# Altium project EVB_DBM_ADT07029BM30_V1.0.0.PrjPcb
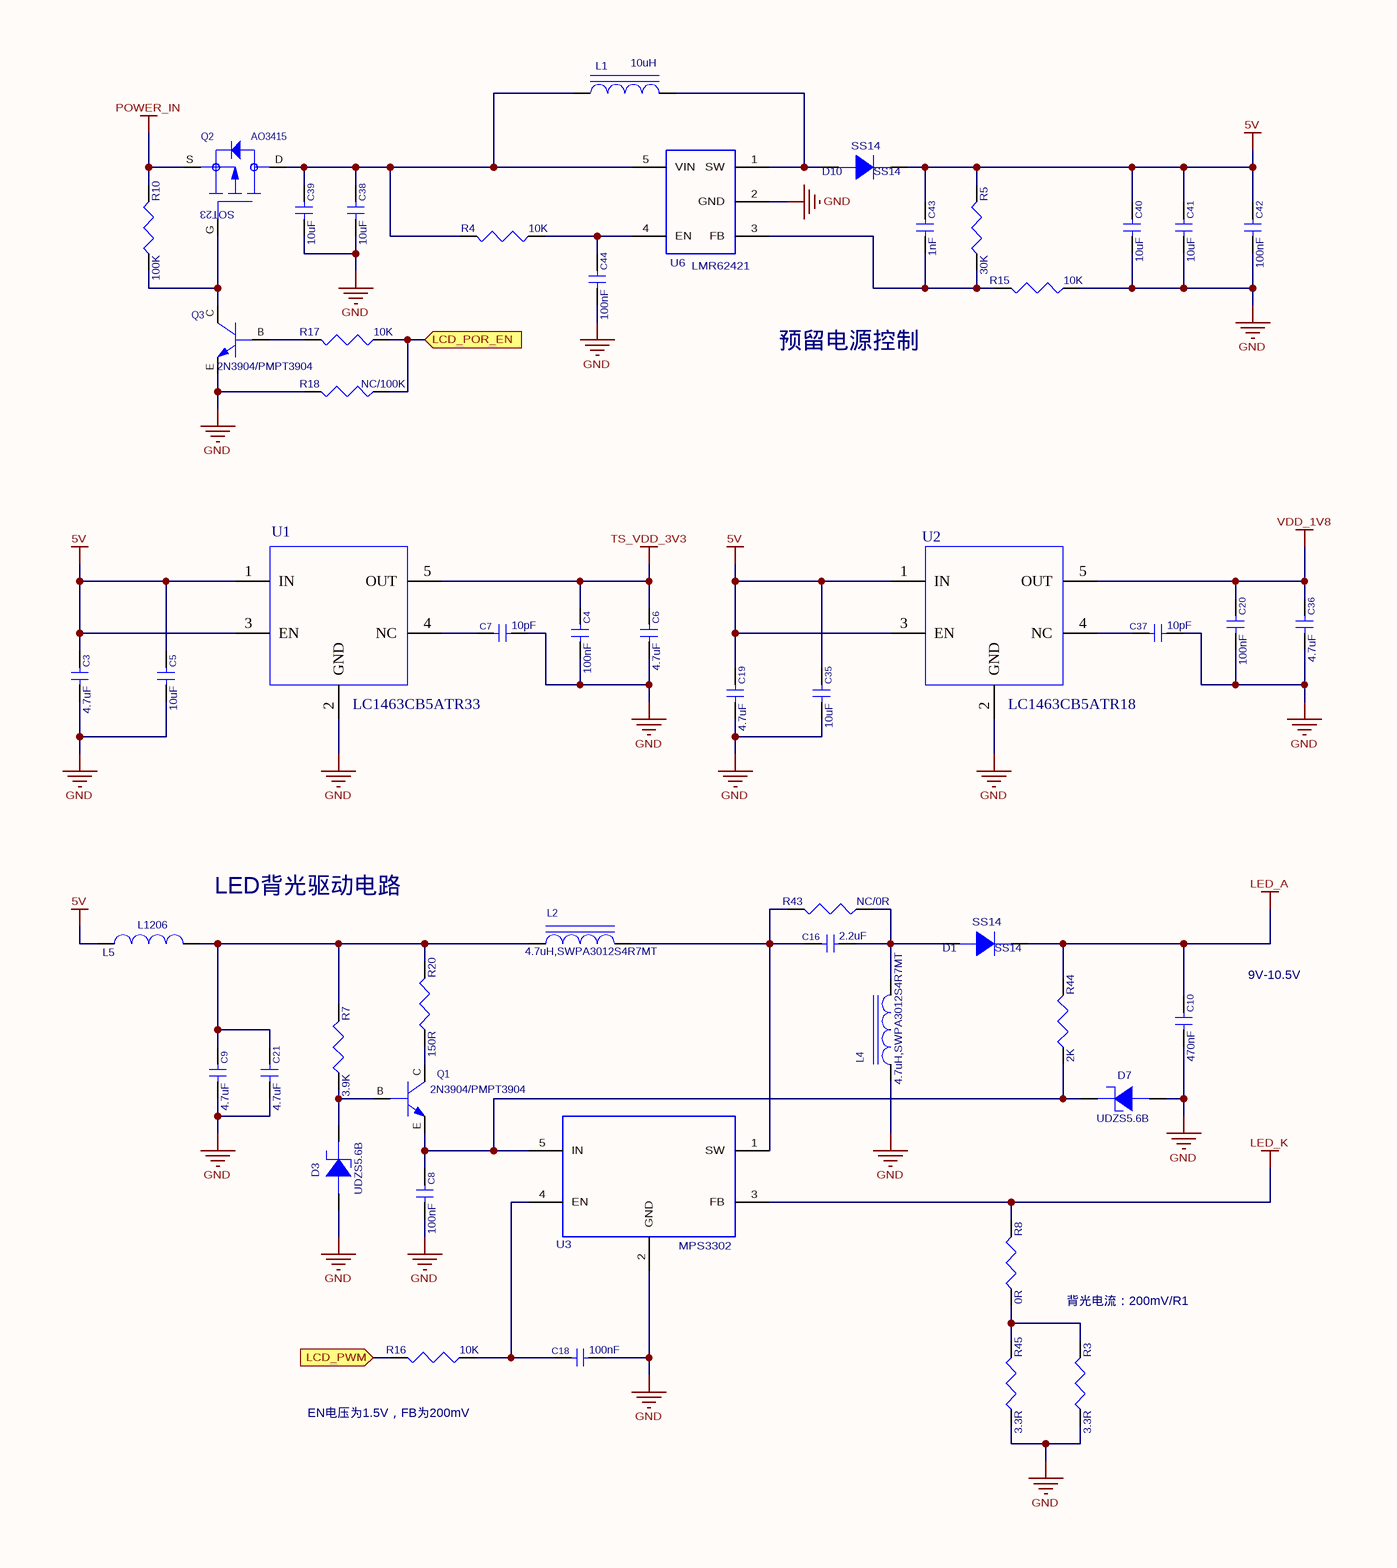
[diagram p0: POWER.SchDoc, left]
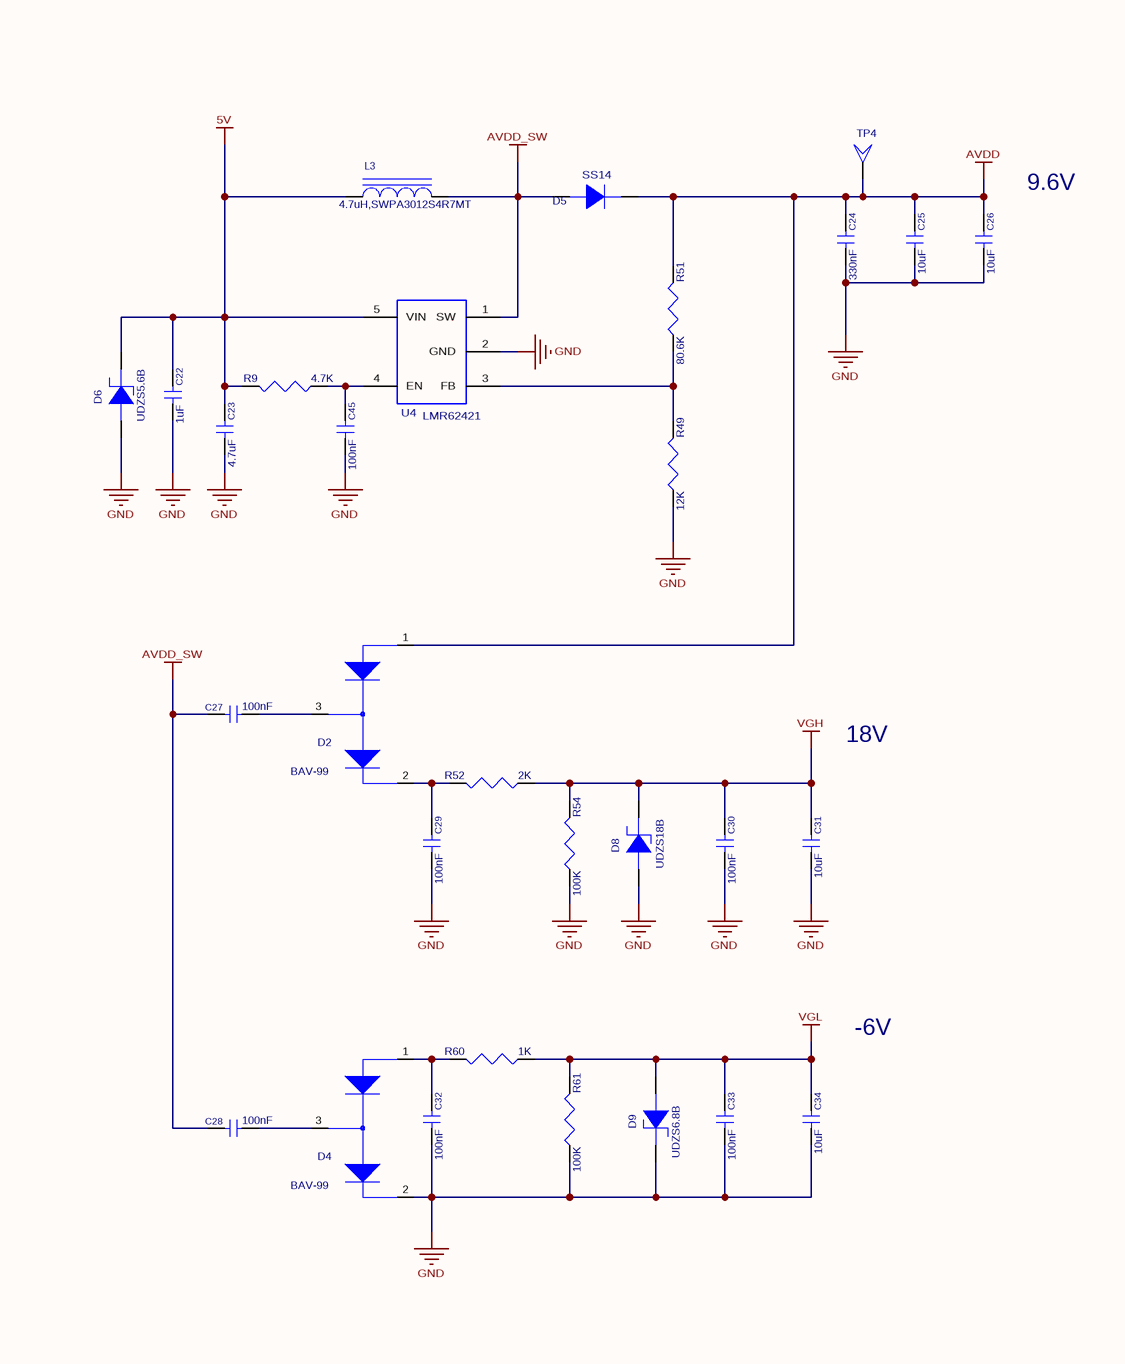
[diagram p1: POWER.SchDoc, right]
2 sheets, 113 parts. Net scope: flat (ports and power ports of the same name join across sheets).
Sheets:
  POWER.SchDoc
  CONNECT.SchDoc

## Sheet POWER.SchDoc: EVB_DBM_ADT07029BM30
size A3; Revision: V1.0.0; SheetNumber: 1; SheetTotal: 2; PCBPartNumber: Sky37D; PCBVersion: V1.0.0; SchModifyDate: 2020-4-27

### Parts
C3  4.7uF  [C0603]
C4  100nF  [C0603]
C5  10uF  [C0603]
C6  4.7uF  [C0603]
C7  10pF  [C0603]
C8  100nF  [C0603]
C9  4.7uF  [C0603]
C10  470nF  [C0603]
C16  2.2uF  [C0603]
C18  100nF  [C0603]
C19  4.7uF  [C0603]
C20  100nF  [C0603]
C21  4.7uF  [C0603]
C22  1uF  [C0603]
C23  4.7uF  [C0603]
C24  330nF  [C0603]
C25  10uF  [C0603]
C26  10uF  [C0603]
C27  100nF  [C0603]
C28  100nF  [C0603]
C29  100nF  [C0603]
C30  100nF  [C0603]
C31  10uF  [C0603]
C32  100nF  [C0603]
C33  100nF  [C0603]
C34  10uF  [C0603]
C35  10uF  [C0603]
C36  4.7uF  [C0603]
C37  10pF  [C0603]
C38  10uF  [C0603]
C39  10uF  [C0603]
C40  10uF  [C0603]
C41  10uF  [C0603]
C42  100nF  [C0603]
C43  1nF  [C0603]
C44  100nF  [C0603]
C45  100nF  [C0603]
D1  SS14  [SS14]
D2  BAV-99  [BAV-99_SOT23_123]
D3  UDZS5.6B  [UDZS6.8B]
D4  BAV-99  [BAV-99_SOT23_123]
D5  SS14  [SS14]  (value not drawn)
D6  UDZS5.6B  [UDZS6.8B]
D7  UDZS5.6B  [UDZS6.8B]
D8  UDZS18B  [UDZS6.8B]
D9  UDZS6.8B  [UDZS6.8B]
D10  SS14  [SS14]
L1  10uH  [L_SWPA4020_4X4MM]
L2  4.7uH,SWPA3012S4R7MT  [L_SWPA3012_3X3MM]
L3  4.7uH,SWPA3012S4R7MT  [L_SWPA3012_3X3MM]
L4  4.7uH,SWPA3012S4R7MT  [L_SWPA3012_3X3MM]
L5  L1206  [L1206]
Q1  value 2N3904/PMPT3904  [2N3904/PMBT3904]  (hidden comment: 2N3904/PMBT3904)
Q2  AO3415  [SOT23_GDS]
Q3  value 2N3904/PMPT3904  [2N3904/PMBT3904]  (hidden comment: 2N3904/PMBT3904)
R3  3.3R  [R0603]
R4  10K  [R0603]
R5  30K  [R0603]
R7  3.9K  [R0603]
R8  0R  [R0603]
R9  4.7K  [R0603]
R10  100K  [R0603]
R15  10K  [R0603]
R16  10K  [R0603]
R17  10K  [R0603]
R18  NC/100K  [R0603]
R20  150R  [R0603]
R43  NC/0R  [R0603]
R44  2K  [R0603]
R45  3.3R  [R0603]
R49  12K  [R0603]
R51  80.6K  [R0603]
R52  2K  [R0603]
R54  100K  [R0603]
R60  1K  [R0603]
R61  100K  [R0603]
TP4  TP40  [TP40]  (value not drawn)
U1  LC1463CB5ATR33  [LC1463CB5ATR18_SOT23-5]
U2  LC1463CB5ATR18  [LC1463CB5ATR18_SOT23-5]
U3  MPS3302  [MPS3302_SOT23-5]
U4  LMR62421  [MPS3302_SOT23-5]
U6  LMR62421  [MPS3302_SOT23-5]

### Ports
LCD_POR_EN (in), LCD_PWM (in)

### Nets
5V: C3.1 C5.1 C19.1 C22.1 C23.1 C35.1 C40.1 C41.1 C42.1 C43.1 D6.2(K) D10.K L3.1 L5.1 R5.2 R9.2 U1.1(IN) U1.3(EN) U2.1(IN) U2.3(EN) U4.5(VIN)
AVDD: C24.1 C25.1 C26.1 D2.1(GND) D5.K R51.2 TP4.1
AVDD_SW: C27.1 C28.1 D5.A L3.2 U4.1(SW)
GND: C3.2 C4.2 C5.2 C6.2 C7.2 C8.2 C9.2 C10.2 C18.2 C19.2 C20.2 C21.2 C22.2 C23.2 C24.2 C25.2 C26.2 C29.2 C30.2 C31.2 C32.2 C33.2 C34.2 C35.2 C36.2 C37.2 C38.2 C39.2 C40.2 C41.2 C42.2 C44.2 C45.2 D3.1(A) D4.2(VDD) D6.1(A) D7.1(A) D8.1(A) D9.2(K) L4.1 Q3.E R3.1 R15.1 R18.2 R45.1 R49.1 R54.1 R61.1 U1.2(GND) U2.2(GND) U3.2(GND) U4.2(GND) U6.2(GND)
LED_A: C10.1 D1.K R44.2
LED_K: R8.2 U3.3(FB)
POWER_IN: Q2.S R10.2
TS_VDD_3V3: C4.1 C6.1 U1.5(OUT)
VDD_1V8: C20.1 C36.1 U2.5(OUT)
VGH: C30.1 C31.1 D8.2(K) R52.1 R54.2
VGL: C33.1 C34.1 D9.1(A) R60.1 R61.2
LCD_POR_EN: R17.1 R18.1 ; port LCD_POR_EN
LCD_PWM: R16.2 ; port LCD_PWM
NetC7_1: C7.1 U1.4(NC)
NetC8_1: C8.1 D7.2(K) Q1.E R44.1 U3.5(IN)
NetC9_1: C9.1 C21.1 L2.1 L5.2 R7.2 R20.2
NetC16_1: C16.1 L2.2 R43.2 U3.1(SW)
NetC16_2: C16.2 D1.A L4.2 R43.1
NetC18_1: C18.1 R16.1 U3.4(EN)
NetC27_2: C27.2 D2.3(SIGNAL)
NetC28_2: C28.2 D4.3(SIGNAL)
NetC29_1: C29.1 D2.2(VDD) R52.2
NetC32_1: C32.1 D4.1(GND) R60.2
NetC37_1: C37.1 U2.4(NC)
NetC38_1: C38.1 C39.1 L1.1 Q2.D R4.2 U6.5(VIN)
NetC43_2: C43.2 R5.1 R15.2 U6.3(FB)
NetC44_1: C44.1 R4.1 U6.4(EN)
NetC45_1: C45.1 R9.1 U4.4(EN)
NetD3_2: D3.2(K) Q1.B R7.1
NetD10_A: D10.A L1.2 U6.1(SW)
NetQ1_C: Q1.C R20.1
NetQ2_G: Q2.G Q3.C R10.1
NetQ3_B: Q3.B R17.2
NetR3_2: R3.2 R8.1 R45.2
NetR49_2: R49.2 R51.1 U4.3(FB)

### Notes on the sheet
- (near C26) 9.6V
- 预留电源控制
- 18V
- (near L5) LED背光驱动电路
- 9V-10.5V
- -6V
- 背光电流：200mV/R1
- (near R16) EN电压为1.5V，FB为200mV

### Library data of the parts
C3 C6 C9 C19 C21 C23 C36 = CC0304752XX: C/C,4.7uF,10V +/-10%,0603; Catalog: 陶瓷电容
C4 C8 C18 C20 C27-C30 C32 C33 C42 C44 C45 = CC0301040XX: C/C,100nF,25V,+/-5%,0603; Catalog: 陶瓷电容
C5 C35 C38-C41 = CC0301064XX: C/C,10uF,6.3V,+/-20%,0603; Catalog: 陶瓷电容
C7 C37 = CC0301000XX: C/C,10pF,25V,+/-5%,0603; Catalog: 陶瓷电容
C10 = CC0304742XX: C/C,470nF,25V,+/-10%,0603; Catalog: 陶瓷电容
C16 = CC0302251XX: C/C,2.2uF,25V,+/-5%,,0603; Catalog: 陶瓷电容
C22 = CC0301052XX: C/C,1uF,50V,+/-5%,0603; Catalog: 陶瓷电容
C24 = CC0303340XX: C/C,330nF,50V,+/-5%,0603; Catalog: 陶瓷电容
C25 C26 C31 C34 = CC0301060XX: C/C,10uF,25V,+/-5%,0603; Catalog: 陶瓷电容
C43 = CC0301020XX: C/C,1nF,25V,+/-5%,0603; Catalog: 陶瓷电容
D1 D5 D10 = DDD0SCH00XX: SS14 DO-214AC 肖特基二极管; Catalog: 二极管
D2 D4 = DD21SSD00XX: Small signal Diodes,onsemi,BAV99LT1G,SOT23; Catalog: 二极管
D3 D6 D7 = DD23ZEN03XX: Zener Diode,UDZS5.6B,5.6V,S0D-323; Catalog: 二极管
D8 = DD23ZEN04XX: 稳压管：Zener Diode,UDZS18B,18V,S0D-323; PCB DECAL: UDZS5.6B; Catalog: 二极管
D9 = DD33ZEN68XX: Zener Diode,UDZS6.8B,6.8V,S0D-323; Catalog: 稳压管
L1 = WL1B01000XX: 10uH,SWPA4020S100MT; SOURCE_PATH: E:\工作目录\ORCAD原理图库\ORCAD元件库\磁珠&电感.OLB; Catalog: 贴片电感
L2-L4 = WL1C04R70XX: Part Number_AK: WL1C02R20XX; SOURCE_PATH: E:\工作目录\ORCAD原理图库\ORCAD元件库\磁珠&电感.OLB; Catalog: 贴片电感
L5 = BE0606010XX: PZ3216D601_L1206,PZ3216D601-1R5TF; SOURCE_PATH: E:\工作目录\ORCAD原理图库\ORCAD元件库\磁珠&电感.OLB; Catalog: 贴片磁珠
Q1 Q3 = TR05NGN00XX: 2N3904/PMBT3904,SOT-23,NPN,GP; PCB DECAL: 2N3904/PMBT3904_SOT23_BCE_NPN; Catalog: 三极管
Q2 = MS052SW02XX: AO3415-sot23,E-P-CH,GP; PCB DECAL: AO3413_SOT23_GDS_P; Catalog: MOS
R3 R45 = CR0303R30XX: Res,3.3R,1/10W,+/-5%,0603; Catalog: 贴片电阻
R4 R15-R17 = CR0310020XX: Res,10K,1/10W,+/-1%,0603; Catalog: 贴片电阻
R5 = CR0303030XX: Res,30K,1/10W,+/-5%,0603; Catalog: 贴片电阻
R7 = CR0339010XX: Res,3.9K,1/10W,+/-1%,0603; Catalog: 贴片电阻
R8 = CR0300000XX: Res,0R,1/10W,+/-5%,0603; Catalog: 贴片电阻
R9 = CR0304720XX: Res,4.7K,1/10W,+/-5%,0603; Catalog: 贴片电阻
R10 R18 R54 R61 = CR0310030XX: Res,100K,1/10W,+/-1%,0603; Catalog: 贴片电阻
R20 = CR0315000XX: Res,150R,1/10W,+/-1%,0603; Catalog: 贴片电阻
R43 = CR0300000XX: Res,0R,1/10W,+/-5%,0603; Remark: NC; Catalog: 贴片电阻
R44 R52 = CR0302020XX: Res,2K,1/10W,+/-5%,0603; Catalog: 贴片电阻
R49 = CR0312020XX: Res,12K,1/10W,+/-1%,0603; Catalog: 贴片电阻
R51 = CR0380620XX: Res,80.6k,1/10W,+/-1%,0603; Catalog: 贴片电阻
R60 = CR0301020XX: Res,1K,1/10W,+/-5%,0603; Catalog: 贴片电阻
U1 = JCSXTPW01X2: PowerIC,Leadchip,LC1463CB5ATR33,3.3V,SOT-23-5; Catalog: 集成电路
U2 = JCSXTPW61XX: PowerIC,Leadchip,LC1463CB5ATR18 ,SOT23,5pin; Catalog: 集成电路
U3 = JCSOTDR00XX: IC MP3302，LCD Drives LED，TSOT23-5; Catalog: 集成电路
U4 U6 = JCSOTPW27XX: PowerIC，TI,LMR62421，SOT-23; PCB DECAL: LMR62421_SOT23-5; Catalog: 集成电路

## Sheet CONNECT.SchDoc: EVB_DBM_ADT07029BM30
size A3; Revision: V1.0.0; SheetNumber: 2; SheetTotal: 2
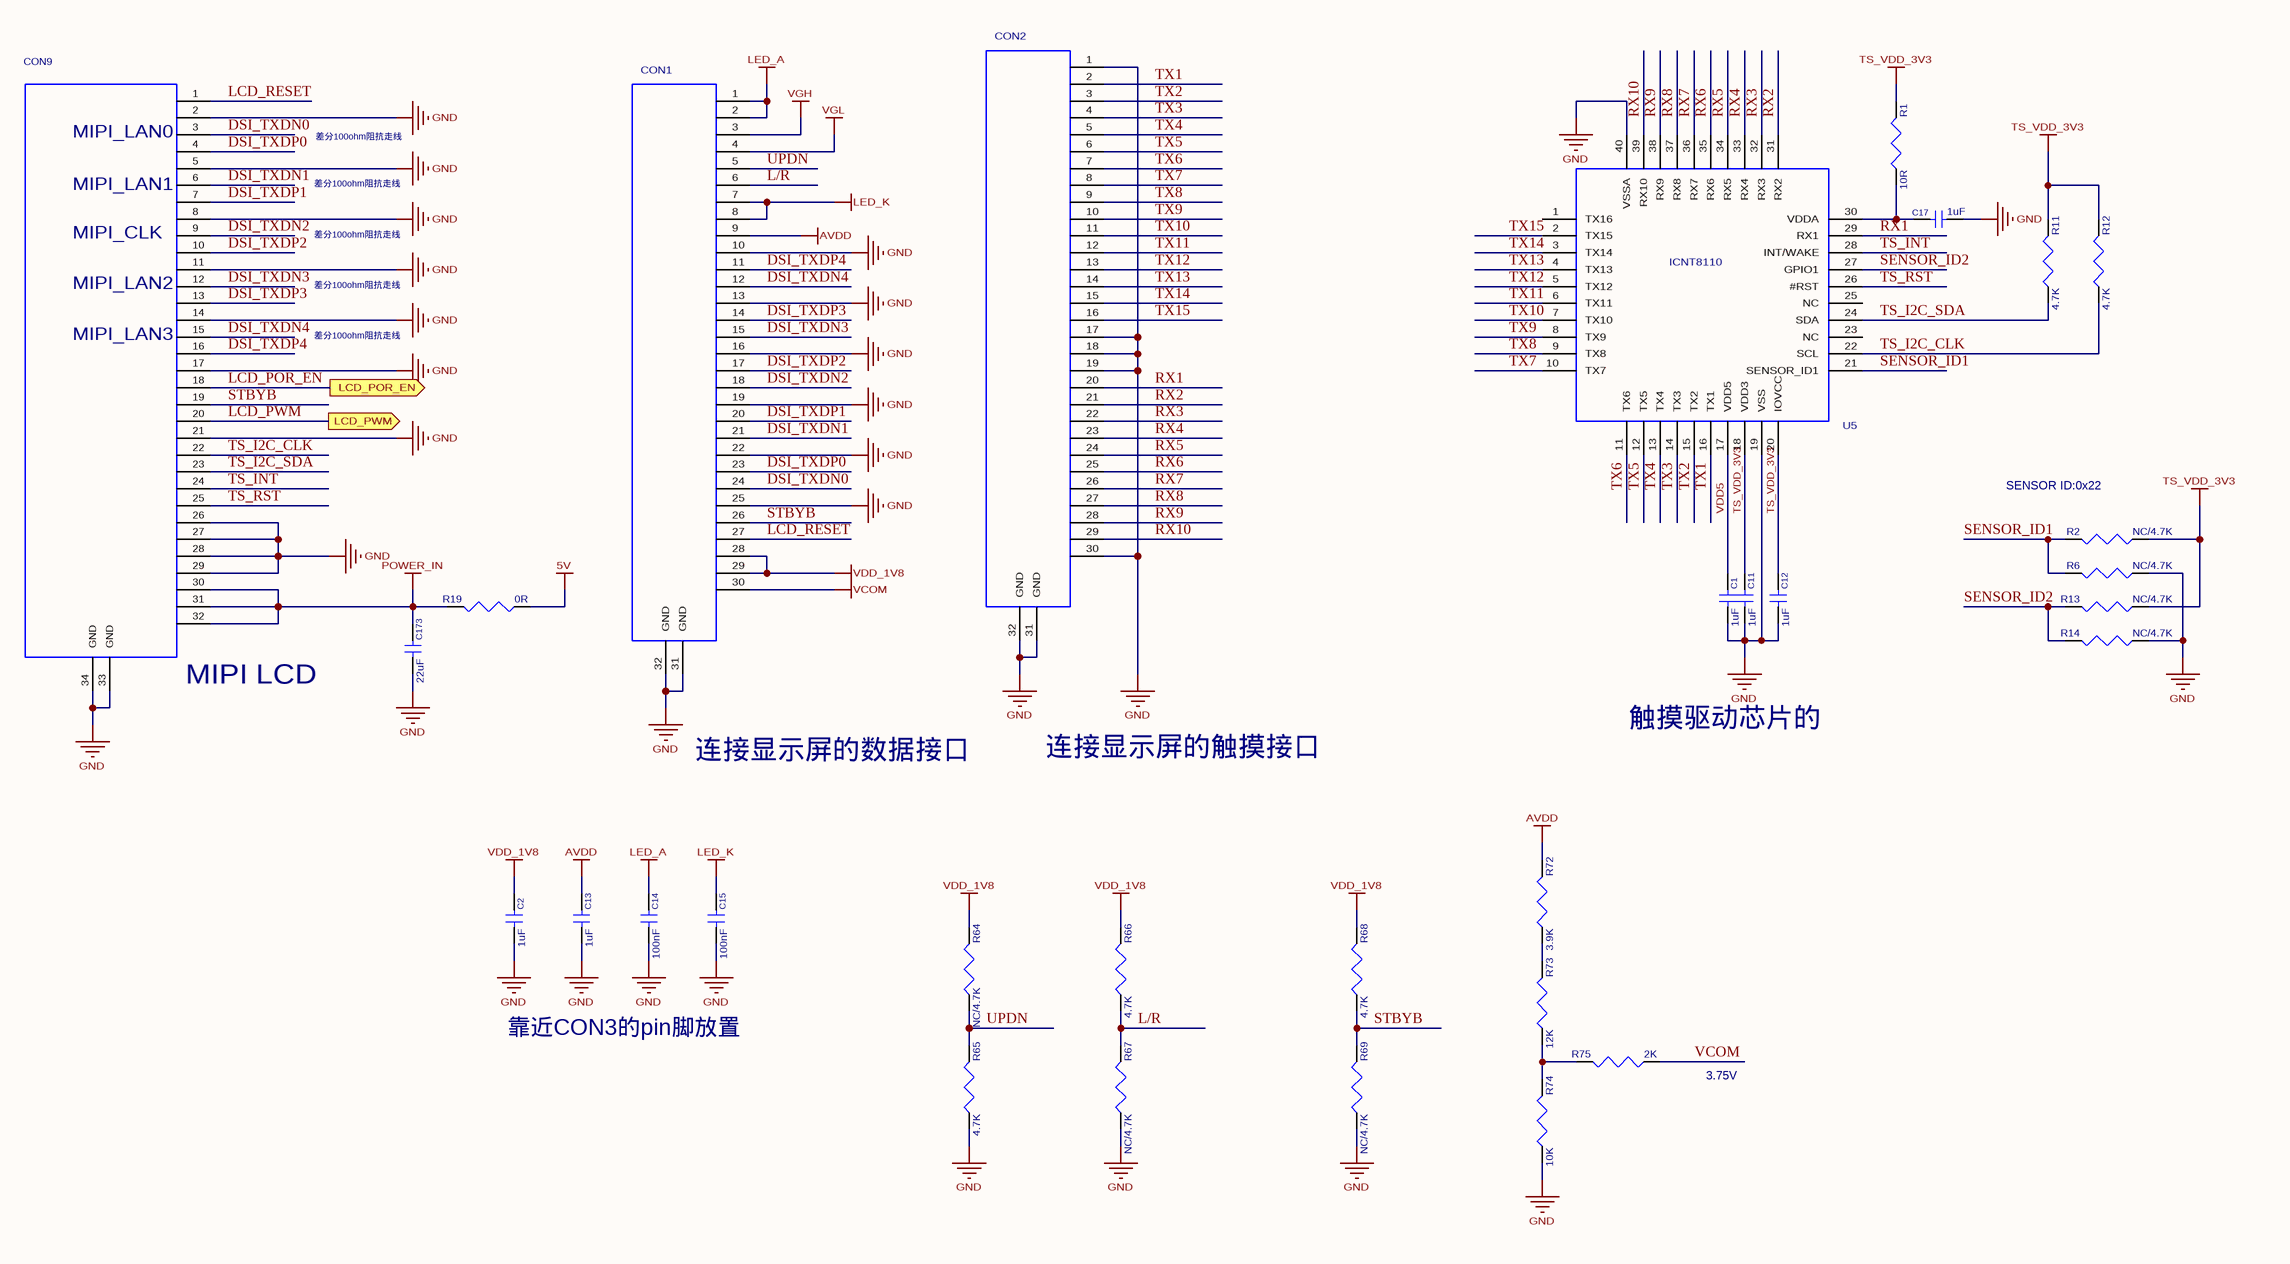
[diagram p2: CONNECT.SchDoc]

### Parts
C1  1uF  [C0603]
C2  1uF  [C0603]
C11  1uF  [C0603]
C12  1uF  [C0603]
C13  1uF  [C0603]
C14  100nF  [C0603]
C15  100nF  [C0603]
C17  1uF  [C0603]
C173  22uF  [C1206]
CON1  CON30_FPC_0.5MM  [CON30_0MM5]  (value not drawn)
CON2  CON30_FPC_0.5MM  [CON30_0MM5]  (value not drawn)
CON9  FPC_32_0MM5  [FPC_32_0MM5]  (value not drawn)
R1  10R  [R0603]
R2  NC/4.7K  [R0603]
R6  NC/4.7K  [R0603]
R11  4.7K  [R0603]
R12  4.7K  [R0603]
R13  NC/4.7K  [R0603]
R14  NC/4.7K  [R0603]
R19  0R  [R1206]
R64  NC/4.7K  [R0603]
R65  4.7K  [R0603]
R66  4.7K  [R0603]
R67  NC/4.7K  [R0603]
R68  4.7K  [R0603]
R69  NC/4.7K  [R0603]
R72  3.9K  [R0603]
R73  12K  [R0603]
R74  10K  [R0603]
R75  2K  [R0603]
U5  ICNT8110  [QFN40_0MM5_5X5MM]  (value not drawn)

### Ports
LCD_POR_EN (out), LCD_PWM (out)

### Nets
5V: R19.1
AVDD: C13.1 CON1.9 R72.2
GND: C1.2 C2.2 C11.2 C12.2 C13.2 C14.2 C15.2 C17.2 C173.2 CON1.10 CON1.13 CON1.16 CON1.19 CON1.22 CON1.25 CON1.31(GND) CON1.32(GND) CON2.1 CON2.17 CON2.18 CON2.19 CON2.30 CON2.31(GND) CON2.32(GND) CON9.2 CON9.5 CON9.8 CON9.11 CON9.14 CON9.17 CON9.21 CON9.26 CON9.27 CON9.28 CON9.29 CON9.33(GND) CON9.34(GND) R6.1 R14.1 R65.1 R67.1 R69.1 R74.1 U5.19(VSS) U5.40(VSSA)
LED_A: C14.1 CON1.1 CON1.2
LED_K: C15.1 CON1.7 CON1.8
POWER_IN: C173.1 CON9.30 CON9.31 CON9.32 R19.2
TS_VDD_3V3: C11.1 C12.1 R1.2 R2.1 R11.2 R12.2 R13.1 U5.18(VDD3) U5.20(IOVCC)
VCOM: CON1.30 R75.1
VDD_1V8: C2.1 CON1.28 CON1.29 R64.2 R66.2 R68.2
VGH: CON1.3
VGL: CON1.4
DSI_TXDN0: CON1.24 CON9.3
DSI_TXDN1: CON1.21 CON9.6
DSI_TXDN2: CON1.18 CON9.9
DSI_TXDN3: CON1.15 CON9.12
DSI_TXDN4: CON1.12 CON9.15
DSI_TXDP0: CON1.23 CON9.4
DSI_TXDP1: CON1.20 CON9.7
DSI_TXDP2: CON1.17 CON9.10
DSI_TXDP3: CON1.14 CON9.13
DSI_TXDP4: CON1.11 CON9.16
L/R: CON1.6 R66.1 R67.2
LCD_POR_EN: CON9.18 ; port LCD_POR_EN
LCD_PWM: CON9.20 ; port LCD_PWM
LCD_RESET: CON1.27 CON9.1
RX1: CON2.20 U5.29(RX1)
RX2: CON2.21 U5.31(RX2)
RX3: CON2.22 U5.32(RX3)
RX4: CON2.23 U5.33(RX4)
RX5: CON2.24 U5.34(RX5)
RX6: CON2.25 U5.35(RX6)
RX7: CON2.26 U5.36(RX7)
RX8: CON2.27 U5.37(RX8)
RX9: CON2.28 U5.38(RX9)
RX10: CON2.29 U5.39(RX10)
SENSOR_ID1: R2.2 R6.2 U5.21(SENSOR_ID1)
SENSOR_ID2: R13.2 R14.2 U5.27(GPIO1)
STBYB: CON1.26 CON9.19 R68.1 R69.2
TS_I2C_CLK: CON9.22 R12.1 U5.22(SCL)
TS_I2C_SDA: CON9.23 R11.1 U5.24(SDA)
TS_INT: CON9.24 U5.28(INT/WAKE)
TS_RST: CON9.25 U5.26(#RST)
TX1: CON2.2 U5.16(TX1)
TX2: CON2.3 U5.15(TX2)
TX3: CON2.4 U5.14(TX3)
TX4: CON2.5 U5.13(TX4)
TX5: CON2.6 U5.12(TX5)
TX6: CON2.7 U5.11(TX6)
TX7: CON2.8 U5.10(TX7)
TX8: CON2.9 U5.9(TX8)
TX9: CON2.10 U5.8(TX9)
TX10: CON2.11 U5.7(TX10)
TX11: CON2.12 U5.6(TX11)
TX12: CON2.13 U5.5(TX12)
TX13: CON2.14 U5.4(TX13)
TX14: CON2.15 U5.3(TX14)
TX15: CON2.16 U5.2(TX15)
UPDN: CON1.5 R64.1 R65.2
VDD5: C1.1 U5.17(VDD5)
NetC17_1: C17.1 R1.1 U5.30(VDDA)
NetR72_1: R72.1 R73.2
NetR73_1: R73.1 R74.2 R75.2

Not connected (* = marked no-connect by the designer): U5 1(TX16) 23(NC) 25(NC)

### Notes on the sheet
- (near CON9) MIPI_LAN0
- (near CON9) MIPI_LAN1
- 差分100ohm阻抗走线
- (near CON9) MIPI_CLK
- (near CON9) MIPI_LAN2
- (near CON9) MIPI_LAN3
- (near R2) SENSOR ID:0x22
- (near CON9) MIPI LCD
- 连接显示屏的数据接口
- 连接显示屏的触摸接口
- 触摸驱动芯片的
- 靠近CON3的pin脚放置
- (near R75) 3.75V

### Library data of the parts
C1 C2 C11-C13 C17 = CC0301055XX: C/C,1uF,16V,+/-10%,0603; Catalog: 陶瓷电容
C14 C15 = CC0301040XX: C/C,100nF,25V,+/-5%,0603; Catalog: 陶瓷电容
C173 = CC0602260XX: C/C,22uF,10V,+/-5%,1206; Catalog: 陶瓷电容
CON1 CON2 = CNFPF3002XX: 连接器 FPC连接器 FPC0.5mm -30P H1.0mm 前插后掀；; Catalog: Connector
CON9 = CNFPF3201XX: FPC连接器，32P，0.5mm，翻盖式，下接，H=2mm; PCB DECAL: CON32_0MM5; Catalog: Connector
R1 = CR0301000XX: Res,10R,1/10W,+/-5%,0603; Catalog: 贴片电阻
R2 R6 R13 R14 R64 R67 R69 = CR0304720XX: Res,4.7K,1/10W,+/-5%,0603; Remark: NC; Catalog: 贴片电阻
R11 R12 R65 R66 R68 = CR0304720XX: Res,4.7K,1/10W,+/-5%,0603; Catalog: 贴片电阻
R19 = CR0600000XX: Res,0R,1/4W,+/-5%,1206; Catalog: 贴片电阻
R72 = CR0339010XX: Res,3.9K,1/10W,+/-1%,0603; Catalog: 贴片电阻
R73 = CR0312020XX: Res,12K,1/10W,+/-1%,0603; Catalog: 贴片电阻
R74 = CR0310020XX: Res,10K,1/10W,+/-1%,0603; Catalog: 贴片电阻
R75 = CR0302020XX: Res,2K,1/10W,+/-5%,0603; Catalog: 贴片电阻
U5 = JCQFNVP01XX: Capacitive Touch Sensor Controller，ICNT8110 QFN40_5*5; Catalog: 集成电路

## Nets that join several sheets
5V: POWER (21 pins), CONNECT (R19.1)
AVDD: POWER (7 pins), CONNECT (C13.1 CON1.9 R72.2)
GND: POWER (53 pins), CONNECT (45 pins)
LED_A: POWER (C10.1 D1.K R44.2), CONNECT (C14.1 CON1.1 CON1.2)
LED_K: POWER (R8.2 U3.3), CONNECT (C15.1 CON1.7 CON1.8)
POWER_IN: POWER (Q2.S R10.2), CONNECT (5 pins)
TS_VDD_3V3: POWER (C4.1 C6.1 U1.5), CONNECT (9 pins)
VDD_1V8: POWER (C20.1 C36.1 U2.5), CONNECT (6 pins)
VGH: POWER (5 pins), CONNECT (CON1.3)
VGL: POWER (5 pins), CONNECT (CON1.4)
LCD_POR_EN: POWER (R17.1 R18.1), CONNECT (CON9.18)
LCD_PWM: POWER (R16.2), CONNECT (CON9.20)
